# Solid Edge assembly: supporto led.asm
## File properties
Author: f_grande
Template: Normal.asm
Last saved by: f_grande
Revision: 4
Application: Solid Edge
Tipo di contenuto documento: 1
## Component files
Parte10.par
LED.asm
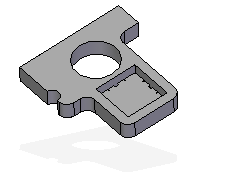
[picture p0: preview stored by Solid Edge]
